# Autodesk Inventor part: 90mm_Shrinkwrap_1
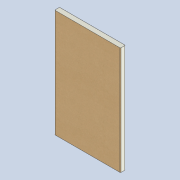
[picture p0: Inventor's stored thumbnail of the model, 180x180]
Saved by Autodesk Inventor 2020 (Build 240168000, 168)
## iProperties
Created: 2020-11
Part Number: 90mm_Shrinkwrap_1
Material: Generic
Document SubType Name: Modeling
Designer: Yolande
Density: 1 g/cm^3
Appearance: Default
description: 0:0:Lambdaboard 90mm Kraft
manufacturer: 0:0:Lambdaboard T/A Rigiifoam
model: 0:0:
url: 0:0:www.lambdaboard.com
Author: Yolande
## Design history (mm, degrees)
derived "90mm.iam"
body "Solid1"
node "Lambdaboard 90mm Kraft.ipt:1" dims "d0" = 10
